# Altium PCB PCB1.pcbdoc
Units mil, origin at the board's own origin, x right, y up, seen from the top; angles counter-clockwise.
Board outline 2670.35 x 3649.61 mil, 2 copper layers (Top Layer, Bottom Layer); 40 components, 34 nets, 176 pads, 47 vias.
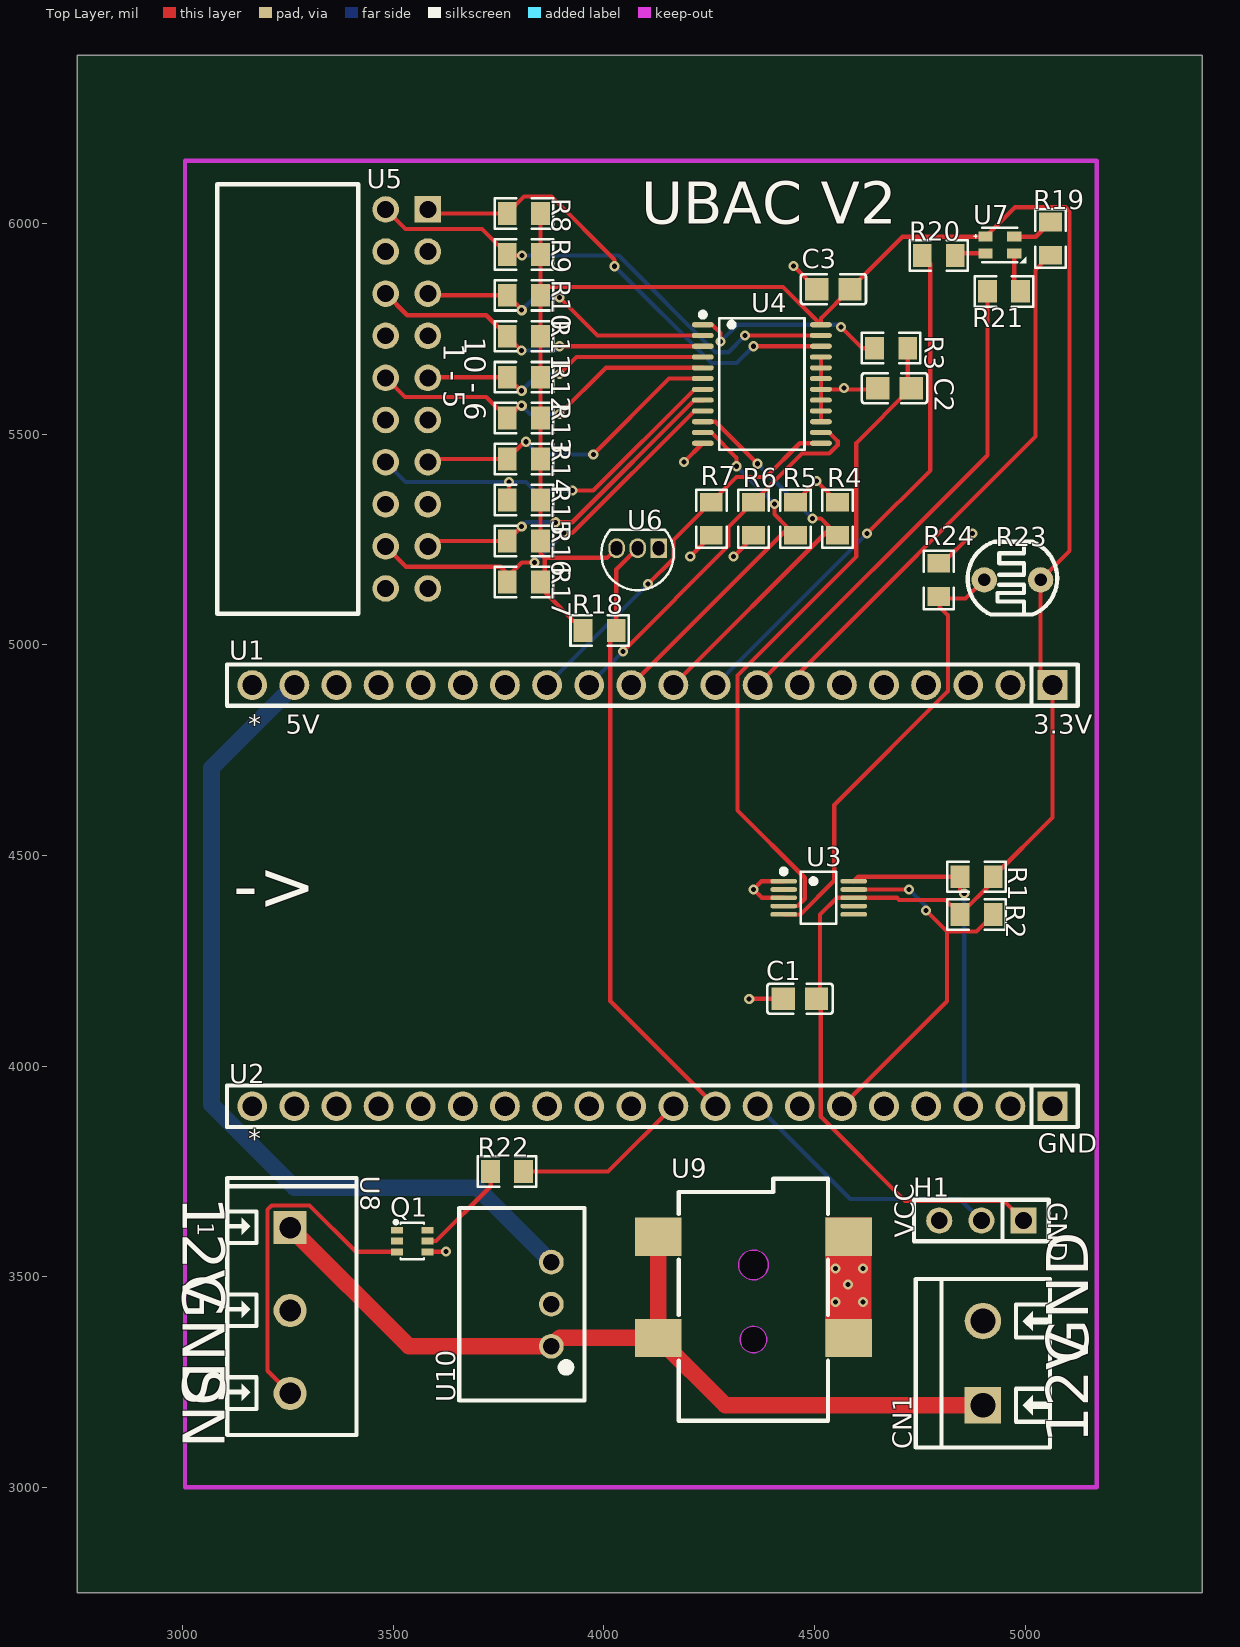
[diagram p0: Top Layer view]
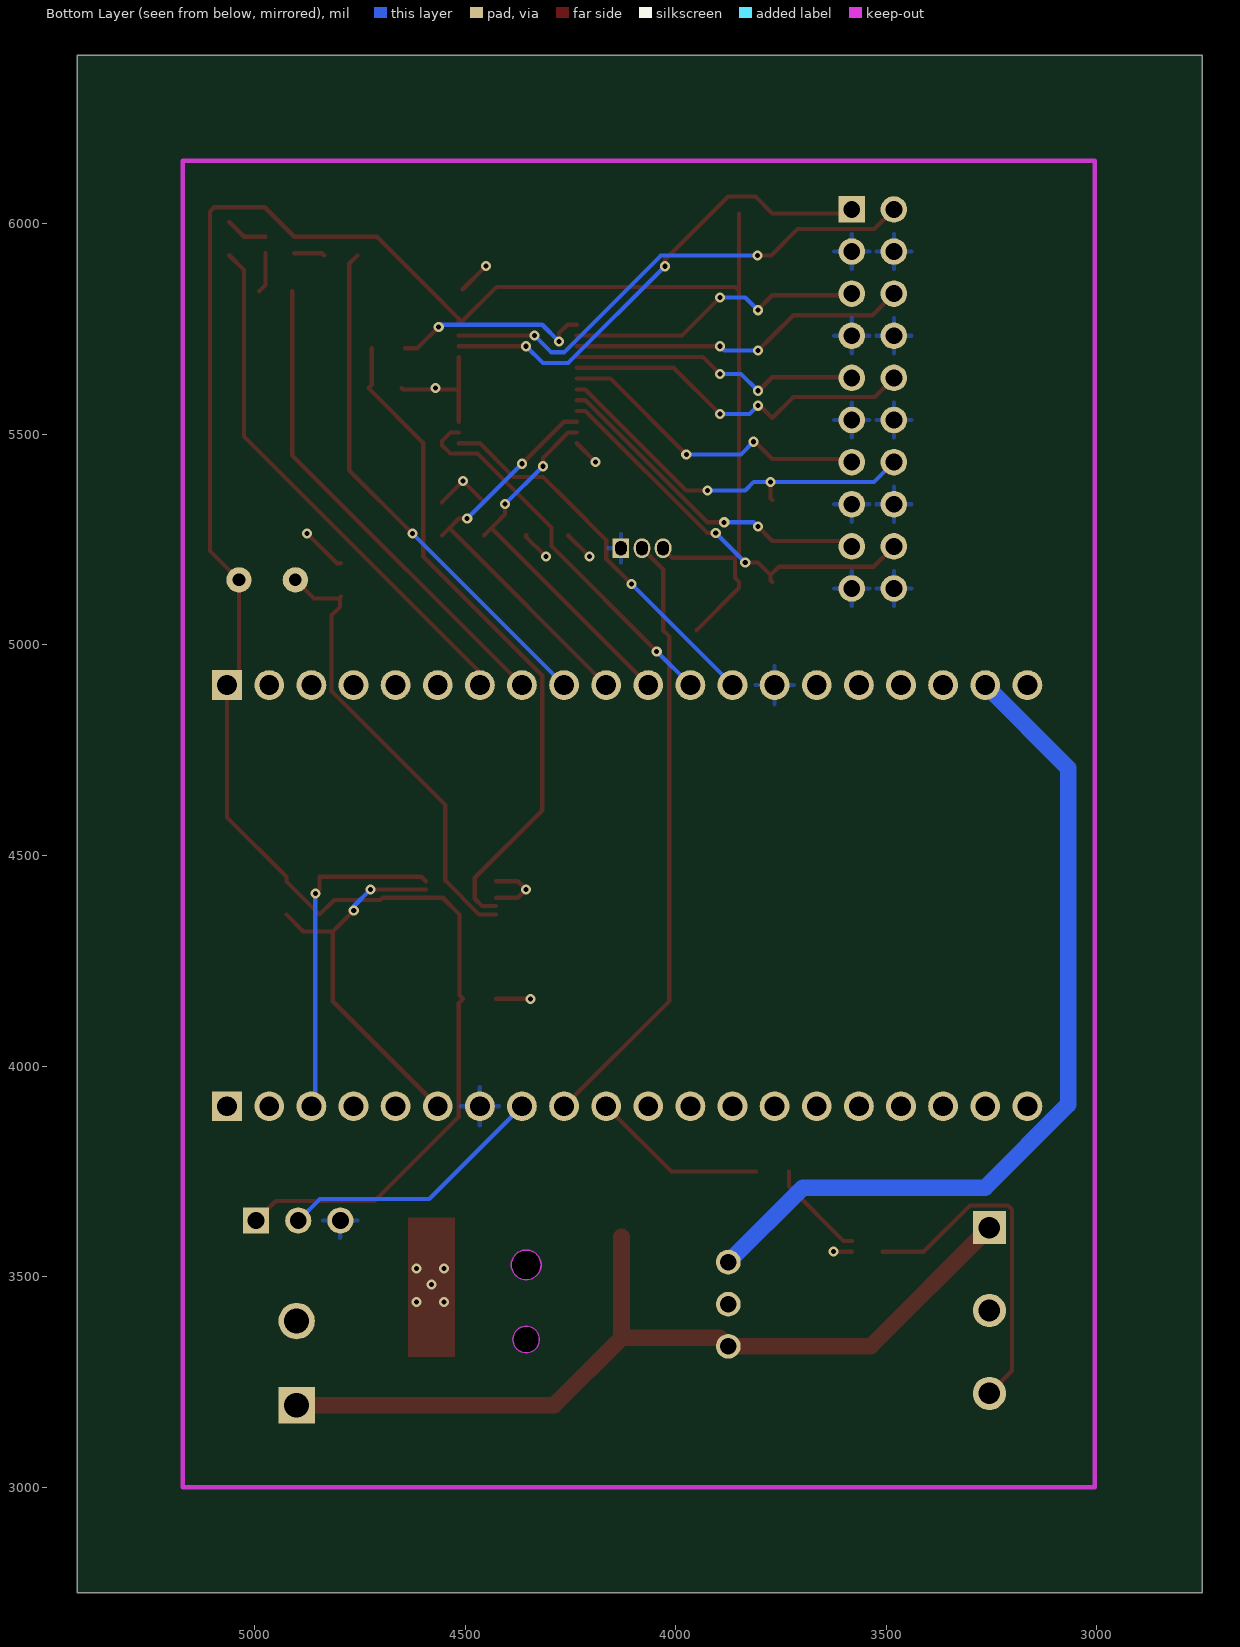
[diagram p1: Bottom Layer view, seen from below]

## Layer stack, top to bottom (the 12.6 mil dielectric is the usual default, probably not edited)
Top Layer: signal copper (thickness not stored)
Dielectric: dielectric 12.6, FR-4, Dk 4.8
Bottom Layer: signal copper (thickness not stored)

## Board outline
5420.35,2750 2750,2750 2750,6399.61 5420.35,6399.61

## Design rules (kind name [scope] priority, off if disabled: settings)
BoardOutlineClearance copperThickness1oz [All] p0: genericclearance=10 ignorepadtopadclearanceinfootprint=FALSE except(0: Arc-SplitContinuation Track-SplitContinuation SMDPad-SplitContinuation THPad-SplitContinuation Via-SplitContinuation Fill-SplitContinuation Poly-SplitContinuation Region-SplitContinuation Text-SplitContinuation; 6: Track-CutoutEdge SMDPad-CutoutEdge THPad-CutoutEdge Via-CutoutEdge Region-CutoutEdge; 11.8: Track-OutlineEdge SMDPad-OutlineEdge THPad-OutlineEdge Via-OutlineEdge Fill-OutlineEdge Region-OutlineEdge Poly-OutlineEdge Text-OutlineEdge Fill-CutoutEdge)
BoardOutlineClearance copperThickness2oz [All] p0: genericclearance=10 ignorepadtopadclearanceinfootprint=FALSE except(0: Arc-SplitContinuation Track-SplitContinuation SMDPad-SplitContinuation THPad-SplitContinuation Via-SplitContinuation Fill-SplitContinuation Poly-SplitContinuation Region-SplitContinuation Text-SplitContinuation; 6: Track-CutoutEdge SMDPad-CutoutEdge THPad-CutoutEdge Via-CutoutEdge Region-CutoutEdge; 11.8: Track-OutlineEdge SMDPad-OutlineEdge THPad-OutlineEdge Via-OutlineEdge Fill-OutlineEdge Region-OutlineEdge Poly-OutlineEdge Text-OutlineEdge Fill-CutoutEdge)
Clearance copperThickness1oz [(InNet('MUX_SELECT_0') OR InNet('GND') OR InNet('MUX_SELECT_3') OR InNet('MUX_SELECT_1') OR InNet('TEMP9') OR InNet('VCC') OR InNet('SDA') OR InNet('MUX_SELECT_2') OR InNet('SCL') OR InNet('TEMP8') OR InNet('TEMP7') OR InNet('TEMP6') OR InNet('TEMP5') OR InNet('TEMP4') OR InNet('TEMP3') OR InNet('TEMP2') OR InNet('TEMP1') OR InNet('TEMP10') OR InNet('$3N394') OR InNet('FAN_CTRL') OR InNet('NTC_ADC') OR InNet('NTC_MUX') OR InNet('DH11_DATA') OR InNet('12V') OR InNet('DS18B20_DATA') OR InNet('LED_R') OR InNet('LED_G') OR InNet('LED_B') OR InNet('5V') OR InNet('$3N812') OR InNet('$6N1989') OR InNet('$6N2479') OR InNet('LDR') OR InNet('$6N2851'))] p1: gap=7 ignorepadtopadclearanceinfootprint=FALSE except(4: Track-Track; 6: Track-SMDPad SMDPad-SMDPad Track-THPad SMDPad-THPad THPad-THPad Track-Via SMDPad-Via THPad-Via Via-Via SMDPad-Fill THPad-Fill Via-Fill Fill-Fill Track-Region SMDPad-Region THPad-Region Via-Region Region-Region Track-Poly SMDPad-Poly THPad-Poly Via-Poly Fill-Poly Region-Poly Poly-Poly Track-Text SMDPad-Text THPad-Text Via-Text Fill-Text Region-Text Poly-Text Text-Text; 6.9: Track-Hole SMDPad-Hole THPad-Hole Via-Hole Fill-Hole Region-Hole Poly-Hole Text-Hole Sheet-Hole; 11.8: Track-Fill Fill-Region Track-Sheet SMDPad-Sheet THPad-Sheet Via-Sheet Fill-Sheet Region-Sheet Poly-Sheet Text-Sheet)
Clearance copperThickness2oz [All] p1: gap=7 ignorepadtopadclearanceinfootprint=FALSE except(6: Track-SMDPad SMDPad-SMDPad Track-THPad SMDPad-THPad THPad-THPad Track-Via SMDPad-Via THPad-Via Via-Via SMDPad-Fill THPad-Fill Via-Fill Fill-Fill Track-Region SMDPad-Region THPad-Region Via-Region Region-Region Track-Poly SMDPad-Poly THPad-Poly Via-Poly Fill-Poly Region-Poly Poly-Poly Track-Text SMDPad-Text THPad-Text Via-Text Fill-Text Region-Text Poly-Text Text-Text; 6.9: Track-Hole SMDPad-Hole THPad-Hole Via-Hole Fill-Hole Region-Hole Poly-Hole Text-Hole Sheet-Hole; 8: Track-Track; 11.8: Track-Fill Fill-Region Track-Sheet SMDPad-Sheet THPad-Sheet Via-Sheet Fill-Sheet Region-Sheet Poly-Sheet Text-Sheet)
DiffPairsRouting differentialPair [All] p1: maxuncoupledlength=10 minlimit=6 maxlimit=6 mostfreqgap=6 toplayer_minwidth=5 toplayer_prefwidth=10 toplayer_maxwidth=100 bottomlayer_minwidth=5 bottomlayer_prefwidth=10 bottomlayer_maxwidth=100
PasteMaskExpansion pasteMaskExpansion [All] p1: expansion=0
PlaneConnect innerPlane [All] p1: planeconnectstyle=Relief reliefexpansion=20 reliefentries=4 reliefconductorwidth=10 reliefairgap=10
PolygonConnect copperRegion [All] p1: connectstyle=Relief reliefentries=4 reliefconductorwidth=10 polygonreliefangle="90 Angle" airgapwidth=10
RoutingVias viaSize [All] p1: viastyle="Through Hole" holewidth=12.0078 minholewidth=11.811 maxholewidth=248.0314 width=24.0158 minwidth=19.685 maxwidth=393.7008
SolderMaskExpansion solderMaskExpansion [All] p1: useseparateexpansions=TRUE expansion=2 expansionbottom=2
Width copperThickness1oz [All] p1: maxlimit=100 minlimit=5 preferedwidth=10
Width copperThickness2oz [All] p1: maxlimit=100 minlimit=8 preferedwidth=10
Width copperThickness1ozLarge [All] p1: maxlimit=100 minlimit=31 preferedwidth=39

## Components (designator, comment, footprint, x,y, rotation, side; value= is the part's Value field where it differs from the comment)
C1 "CL21B104KCFNNNE" C0805 4465.49,4159.85 r0 top
C2 "CL21B105KBFNNNE" C0805 4690,5609.68 r0 top
C3 "CL21B104KCFNNNE" C0805 4545,5844.61 r0 top
CN1 "1729128_C7509570" CONN-TH_2P-P5.08_1729128 4900,3294.61 r90 top
H1 "PM254V-11-03-H85" HDR-TH_3P-P2.54-V-F 4896.24,3633.3 r180 top
Q1 "MBT3904DW1T1G" SOT-363_L2.0-W1.3-P0.65-LS2.1-TL 3545,3584.61 r0 top
R1 "0805W8F4701T5E" R0805 4885,4449.61 r180 top
R2 "0805W8F4701T5E" R0805 4885,4359.61 r180 top
R3 "0805W8F2200T5E" R0805 4682.03,5704.61 r180 top
R4 "0805W8F1003T5E" R0805 4555,5299.61 r90 top
R5 "0805W8F1003T5E" R0805 4455,5299.61 r90 top
R6 "0805W8F1003T5E" R0805 4355,5299.61 r90 top
R7 "0805W8F1003T5E" R0805 4255,5299.61 r90 top
R8 "TC0525B5602T5G" R0805 3810,6024.61 r180 top
R9 "TC0525B5602T5G" R0805 3810,5927.38 r180 top
R10 "TC0525B5602T5G" R0805 3810,5830.16 r180 top
R11 "TC0525B5602T5G" R0805 3810,5732.94 r180 top
R12 "TC0525B5602T5G" R0805 3810,5635.72 r180 top
R13 "TC0525B5602T5G" R0805 3810,5538.5 r180 top
R14 "TC0525B5602T5G" R0805 3810,5441.27 r180 top
R15 "TC0525B5602T5G" R0805 3810,5344.05 r180 top
R16 "TC0525B5602T5G" R0805 3810,5246.83 r180 top
R17 "TC0525B5602T5G" R0805 3810,5149.61 r180 top
R18 "0805W8F4701T5E" R0805 3990,5034.61 r180 top
R19 "0805W8F1000T5E_C17408" R0805 5060,5964.61 r270 top
R20 "0805W8F1000T5E_C17408" R0805 4795,5924.61 r0 top
R21 "0805W8F1800T5E" R0805 4950,5839.61 r180 top
R22 "FRC0805J102 TS" R0805 3770,3749.61 r180 top
R23 "GL5539" RES-TH_L5.1-W4.3-P3.40-D0.5 4970,5154.61 r270 top
R24 "0805W8F1002T5E" R0805 4795,5154.61 r90 top
U1 "ZX-PM2.54-1-20PY" HDR-TH_20P-P2.54-V-F 4115,4904.61 r180 top
U2 "ZX-PM2.54-1-20PY" HDR-TH_20P-P2.54-V-F 4115,3904.61 r180 top
U3 "ADS1115IDGSR" MSOP-10_L3.0-W3.0-P0.50-LS5.0-BL 4510,4399.61 r270 top
U4 "CD74HC4067SM96" SSOP-24_L8.1-W5.3-P0.65-LS7.8-BL 4375,5619.61 r270 top
U5 "HX FH254-02-10-W-H8.5 right angle pin header" HDR-TH_20P-P2.54-H-F-R2-C10-S2.54-W12.7 3531.85,5584.06 r270 top
U6 "DS18B20" TO-92-3_L4.5-W3.5-P1.27-L 4080,5229.61 r180 top
U7 "XL-B2020RGBA-HF" LED-SMD_4P-L2.1-W2.1-P1.0-BL 4940,5949.61 r0 top
U8 "MX126-5.0-03P-GN01-Cu-S-A" CONN-TH_3P-P5.00_MAX_MX126-5.0-GN01-03P-CU-S-A 3255,3419.61 r270 top
U9 "DC-050-20" DC-IN-SMD_DC-050-20A 4355,3474.61 r180 top
U10 "K7805-1000R3" PWRM-TH_YLPTEC_K78XX-1000R3 3875,3434.61 r90 top

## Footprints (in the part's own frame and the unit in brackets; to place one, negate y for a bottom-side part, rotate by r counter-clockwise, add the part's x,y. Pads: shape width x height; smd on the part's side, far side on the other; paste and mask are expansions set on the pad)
C0805 [mm]
  rect 1.41x1.35 smd: 1(-1,0) 2(1,0)
  silkscreen extent -1.96,-0.9 1.96,0.9
CONN-TH_2P-P5.08_1729128 [mm]
  rect 2.2x2.2 hole 1.5: 1(-2.54,0)
  round 2.2 hole 1.5: 2(2.54,0)
  silkscreen extent -5.08,-4.05 5.08,4.05
CONN-TH_3P-P5.00_MAX_MX126-5.0-GN01-03P-CU-S-A [mm]
  rect 2x2 hole 1.3: 1(-5,0)
  round 2 hole 1.3: 2(0,0) 3(5,0)
  silkscreen extent -8,-3.81 7.5,4
DC-IN-SMD_DC-050-20A [mm]
  rect 2.8x2.3 smd: 1(5.75,3.05) 1(5.75,-3.05) 2(-5.75,3.05) 3(-5.75,-3.05)
  Board Outline Layer circle w0.005: c0,3.15 r0.8
  Board Outline Layer circle w0.005: c0,-1.35 r0.9
  Board Outline Layer region: -0.8,3.15 -0.721,3.497 -0.499,3.775 -0.178,3.93 0.178,3.93 0.499,3.775 0.721,3.497 0.8,3.15 0.8,3.15 0.721,2.803 0.499,2.525 0.178,2.37 -0.178,2.37 -0.499,2.525 -0.721,2.803 -0.8,3.15
  Board Outline Layer region: -0.9,-1.35 -0.811,-0.96 -0.561,-0.646 -0.2,-0.473 0.2,-0.473 0.561,-0.646 0.811,-0.96 0.9,-1.35 0.9,-1.35 0.811,-1.741 0.561,-2.054 0.2,-2.228 -0.2,-2.228 -0.561,-2.054 -0.811,-1.741 -0.9,-1.35
  Multi-Layer board cut-out: -0.8,3.15 -0.721,3.497 -0.499,3.775 -0.178,3.93 0.178,3.93 0.499,3.775 0.721,3.497 0.8,3.15 0.8,3.15 0.721,2.803 0.499,2.525 0.178,2.37 -0.178,2.37 -0.499,2.525 -0.721,2.803 -0.8,3.15
  Multi-Layer board cut-out: -0.9,-1.35 -0.811,-0.96 -0.561,-0.646 -0.2,-0.473 0.2,-0.473 0.561,-0.646 0.811,-0.96 0.9,-1.35 0.9,-1.35 0.811,-1.741 0.561,-2.054 0.2,-2.228 -0.2,-2.228 -0.561,-2.054 -0.811,-1.741 -0.9,-1.35
  silkscreen extent -4.5,-6.55 4.5,8.05
HDR-TH_3P-P2.54-V-F [mil]
  rect 62x62 hole 40.16: 1(-100,0)
  round 62 hole 40.16: 2(0,0) 3(100,0)
  silkscreen extent -160,-49 160,49
HDR-TH_20P-P2.54-H-F-R2-C10-S2.54-W12.7 [mm]
  rect 1.6x1.6 hole 1.02: 1(-11.43,1.27)
  round 1.6 hole 1.02: 2(-11.43,-1.27) 3(-8.89,1.27) 4(-8.89,-1.27) 5(-6.35,1.27) 6(-6.35,-1.27) 7(-3.81,1.27) 8(-3.81,-1.27) 9(-1.27,1.27) 10(-1.27,-1.27) 11(1.27,1.27) 12(1.27,-1.27) 13(3.81,1.27) 14(3.81,-1.27) 15(6.35,1.27) 16(6.35,-1.27) 17(8.89,1.27) 18(8.89,-1.27) 19(11.43,1.27) 20(11.43,-1.27)
  silkscreen extent -12.95,-11.43 12.95,-2.92
HDR-TH_20P-P2.54-V-F [mm]
  rect 1.8x1.8 hole 1.2: 1(-24.13,0)
  round 1.8 hole 1.2: 2(-21.59,0) 3(-19.05,0) 4(-16.51,0) 5(-13.97,0) 6(-11.43,0) 7(-8.89,0) 8(-6.35,0) 9(-3.81,0) 10(-1.27,0) 11(1.27,0) 12(3.81,0) 13(6.35,0) 14(8.89,0) 15(11.43,0) 16(13.97,0) 17(16.51,0) 18(19.05,0) 19(21.59,0) 20(24.13,0)
  silkscreen extent -25.65,-1.25 25.65,1.25
LED-SMD_4P-L2.1-W2.1-P1.0-BL [mm]
  rect 0.85x0.6 smd: 1(0.87,-0.5) 2(-0.87,-0.5) 3(-0.87,0.5) 4(0.87,0.5)
  silkscreen extent -1.58,-1.1 1.6,1.05
MSOP-10_L3.0-W3.0-P0.50-LS5.0-BL [mm]
  oval 0.28x1.62 smd: 1(-1,-2.11) 2(-0.5,-2.11) 3(0,-2.11) 4(0.5,-2.11) 5(1,-2.11) 6(1,2.11) 7(0.5,2.11) 8(0,2.11) 9(-0.5,2.11) 10(-1,2.11)
  silkscreen extent -1.74,-2.26 1.58,1.07
PWRM-TH_YLPTEC_K78XX-1000R3 [mm]
  round 1.5 hole 1: 1(-2.54,0) 2(0,0) 3(2.54,0)
  silkscreen extent -5.8,-2 5.8,5.55
R0805 [mm]
  rect 1.133x1.377 smd: 1(-1,0) 2(1,0)
  silkscreen extent -1.76,-0.92 1.76,0.92
RES-TH_L5.1-W4.3-P3.40-D0.5 [mil]
  round 60 hole 30: 1(0,66.93) 2(0,-66.93)
  silkscreen extent -91,-106 83,106
SOT-363_L2.0-W1.3-P0.65-LS2.1-TL [mm]
  rect 0.7x0.42 smd: 1(-0.92,0.65) 2(-0.92,0) 3(-0.92,-0.65) 4(0.92,-0.65) 5(0.92,0) 6(0.92,0.65)
  silkscreen extent -1.09,-1.1 0.7,1.24
SSOP-24_L8.1-W5.3-P0.65-LS7.8-BL [mil]
  oval 12.13x52.13 smd: 1(-140.75,-140.24) 2(-115.16,-140.24) 3(-89.57,-140.24) 4(-63.98,-140.24) 5(-38.39,-140.24) 6(-12.79,-140.24) 7(12.8,-140.24) 8(38.39,-140.24) 9(63.98,-140.24) 10(89.57,-140.24) 11(115.16,-140.24) 12(140.75,-140.24) 13(140.75,140.24) 14(115.16,140.24) 15(89.57,140.24) 16(63.98,140.24) 17(38.39,140.24) 18(12.8,140.24) 19(-12.79,140.24) 20(-38.39,140.24) 21(-63.98,140.24) 22(-89.57,140.24) 23(-115.16,140.24) 24(-140.75,140.24)
  silkscreen extent -171,-146 157,101
TO-92-3_L4.5-W3.5-P1.27-L [mm]
  rect 1x1.2 hole 0.7 slot 0.85 at 90 deg: 1(-1.27,0)
  oval 1x1.2 hole 0.7 slot 0.85 at 90 deg: 2(0,0) 3(1.27,0)
  silkscreen extent -2.19,-1.1 2.19,2.52

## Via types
v1: diameter 24.02, hole 12.01, Top Layer to Bottom Layer, 47 vias

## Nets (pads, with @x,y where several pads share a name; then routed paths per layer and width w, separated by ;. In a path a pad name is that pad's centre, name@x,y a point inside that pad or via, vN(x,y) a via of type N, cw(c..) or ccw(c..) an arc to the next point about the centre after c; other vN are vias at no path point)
5V: U1.19 U10.3 | length 2039.4
  Bottom Layer w39.37: U1.19 3068.15,4707.75 3068.15,3908.38 3265,3711.53 3698.07,3711.53 U10.3
12V: CN1.1 U8.1 U9.1 U10.1 | length 2076.4
  Top Layer w39.37: U8.1 3536.85,3334.61 U10.1 3894.92,3354.53 U9.1@4128.62,3354.53 ; U9.1@4128.62,3594.68 U9.1@4128.62,3354.53 ; CN1.1 4288.54,3194.61 U9.1@4128.62,3354.53
$3N394: Q1.3 U8.3 | length 815.7
  Top Layer w10: U8.3 3201.26,3276.5 3201.26,3659.02 3211.26,3669.02 3301.26,3669.02 3411.26,3559.02 Q1.3
$3N812: Q1.5 R22.2 | length 239.1
  Top Layer w10: Q1.5 3601.22,3584.61 3731.22,3714.61 3731.22,3749.02 R22.2
$6N1989: R19.1 U7.4 | length 100.1
  Top Layer w10: U7.4 5025.31,5969.29 R19.1
$6N2479: R21.1 U7.1 | length 96.6
  Top Layer w10: U7.1 4974.25,5854.73 R21.1
$6N2851: R20.2 U7.2 | length 73.6
  Top Layer w10: R20.2 4839.69,5929.92 U7.2
DH11_DATA: H1.2 U2.8 | length 643.6
  Bottom Layer w10: U2.8 4585,3684.61 4844.93,3684.61 H1.2
DS18B20_DATA: R18.1 U2.9 U6.2 | length 1455.5
  Top Layer w10: U6.2 4029.37,5178.98 R18.1 4015,5020.24 4015,4154.61 U2.9
FAN_CTRL: R22.1 U2.10 | length 419.8
  Top Layer w10: R22.1 4010,3749.61 U2.10
GND: C1.1 C2.1 C3.1 CN1.2 H1.3 Q1.4 R4.2 R5.2 R6.1 R7.1 R24.2 U1.14 U2.1 U2.7 U3.1 U3.3 U4.12 U4.15 U4.16 U4.17 U4.18 U4.19 U4.20 U4.21 U5.3 U5.4 U5.7 U5.8 U5.11 U5.12 U5.15 U5.16 U5.19 U5.20 U6.1 U8.2 U9.2 U9.3 U10.2 | length 1110.1
  Top Layer w10: Q1.4 3625,3559.02 v1(3625,3559.61) ; v1(4190,5434.61) 4190.51,5434.61 U4.12 ; v1(4205,5209.61) 4255,5259.61 R7.1 ; v1(4308.14,5209.61) 4355,5256.47 R6.1 ; v1(4345,4159.61) 4345.24,4159.85 C1.1 ; U3.3 4375,4399.61 v1(4355,4419.61) 4374.37,4438.98 U3.1 ; v1(4450,5899.61) 4450.63,5899.61 C3.1 ; R5.2 v1@4505,5388.98 ; v1(4505,5389.61) v1@4505,5388.98 ; U4.15 U4.16 U4.17 U4.18 ; U4.21 U4.20 U4.19 U4.18 ; R4.2 v1@4505,5388.98 ; C2.1 4647.76,5606.81 U4.18 ; R24.2 4804.37,5193.98 v1(4875,5264.61)
  other v1: 4550,3440.1 4615,3440.1 4580,3481.04 4550,3519.61 4615,3519.61 4570,5609.61
LDR: R23.2 R24.1 U3.5 | length 1073.1
  Top Layer w10: U3.5 4466.93,4360.24 4546.93,4440.24 4546.93,4620.24 4816.93,4890.24 4816.93,5070.24 4796.93,5090.24 R24.1@4796.93,5110.24 ; R24.1 R24.1@4796.93,5110.24 ; R23.2 4858.7,5110.24 R24.1@4796.93,5110.24
LED_B: R20.1 U1.9 | length 1239.3
  Top Layer w10: v1(4625,5264.61) 4775,5414.61 4775,5905.24 R20.1
  Bottom Layer w10: U1.9 v1(4625,5264.61)
LED_G: R19.2 U1.7 | length 1267.1
  Top Layer w10: U1.7 4465,4934.61 5025,5494.61 5025,5890.24 R19.2
LED_R: R21.2 U1.8 | length 1161
  Top Layer w10: U1.8 4910.63,5450.23 R21.2
MUX_SELECT_0: R4.1 U1.10 U4.10 | length 960.9
  Top Layer w10: U1.10 4535,5274.6 R4.1@4535,5280.24 ; U4.10 4265.2,5530.04 v1(4365,5430.24) ; v1(4495,5300.24) 4515,5300.24 R4.1@4535,5280.24 ; R4.1 R4.1@4535,5280.24
  Bottom Layer w10: v1(4365,5430.24) v1(4495,5300.24)
MUX_SELECT_1: R5.1 U1.11 U4.11 | length 875.7
  Top Layer w10: U1.11 4435,5274.6 R5.1@4435,5280.24 ; U4.11@4235,5504.21 4255,5504.21 4315,5444.21 v1(4315,5424.21) ; v1(4405,5334.21) 4405,5310.24 R5.1@4435,5280.24 ; R5.1 R5.1@4435,5280.24
  Bottom Layer w10: v1(4315,5424.21) v1(4405,5334.21)
MUX_SELECT_2: R6.2 U1.12 U4.14 | length 910.1
  Top Layer w10: v1(4045,4984.6) 4295,5234.6 4295,5278.98 R6.2 4470.23,5454.21 4535,5454.21 4555,5474.21 4555,5484.21 4534.76,5504.45 U4.14
  Bottom Layer w10: U1.12 v1(4045,4984.6)
MUX_SELECT_3: R7.2 U1.13 U4.13 | length 914.1
  Top Layer w10: v1(4105,5144.6) 4165,5204.6 4165,5248.98 R7.2 4315,5398.98 4385,5398.98 4464.88,5478.86 U4.13
  Bottom Layer w10: U1.13 v1(4105,5144.6)
NTC_ADC: C2.2 R3.1 U3.4 | length 1605
  Top Layer w10: U3.4 4459.61,4379.92 4476.93,4397.24 4476.93,4447.24 4316.93,4607.24 4316.93,4927.24 4599.37,5209.68 4599.37,5479.68 C2.2 4721.4,5617.65 R3.1
NTC_MUX: R3.2 U4.1 | length 475.8
  Top Layer w10: U4.1 4256.91,5760.36 4276.91,5740.36 v1(4276.91,5720.36) ; v1(4562.66,5754.61) 4612.66,5704.61 R3.2
  Bottom Layer w10: v1(4276.91,5720.36) 4316.91,5760.36 4556.91,5760.36 v1(4562.66,5754.61)
SCL: R1.2 U2.3 U3.10 | length 810
  Top Layer w10: U3.10 4603.7,4449.61 R1.2 4845.63,4419.61 v1(4855.63,4409.61)
  Bottom Layer w10: v1(4855.63,4409.61) 4855.63,3913.98 U2.3
SDA: R2.1 U2.6 U3.9 | length 913.6
  Top Layer w10: U2.6 4814.37,4153.97 4814.37,4319.61 ; U3.9 4593.39,4419.61 v1(4724.37,4419.61) ; v1(4764.37,4369.61) 4814.37,4319.61 ; R2.1 4884.37,4319.61 4814.37,4319.61
  Bottom Layer w10: v1(4724.37,4419.61) 4764.37,4379.61 v1(4764.37,4369.61)
TEMP1: R9.2 U4.23 U5.2 | length 1190.5
  Top Layer w10: U5.2 3528.53,5987.38 3710.63,5987.38 R9.2 3773.25,5924.77 v1(3805.24,5924.77) ; v1(4335.24,5734.77) U4.23
  Bottom Layer w10: v1(3805.24,5924.77) 4035.24,5924.77 4265.24,5694.77 4295.24,5694.77 v1(4335.24,5734.77)
TEMP2: R11.2 U4.3 U5.6 | length 812.9
  Top Layer w10: U5.6 3532.97,5782.94 3720.63,5782.94 R11.2 v1(3804.39,5699.18) ; v1(3894.39,5709.18) U4.3
  Bottom Layer w10: v1(3804.39,5699.18) 3884.39,5699.18 v1(3894.39,5709.18)
TEMP3: R13.2 U4.5 U5.10 | length 858.6
  Top Layer w10: U5.10 3527.41,5588.5 3720.63,5588.5 R13.2 3800.13,5568 v1(3804.76,5568) ; v1(3894.76,5548) 4004.76,5658 U4.5
  Bottom Layer w10: v1(3804.76,5568) 3824.76,5548 v1(3894.76,5548)
TEMP4: R15.2 U4.7 U5.14 | length 924.6
  Top Layer w10: R15.2 3774.76,5348.18 v1(3774.76,5386.81) ; v1(3924.76,5366.81) 3974.76,5366.81 4214.76,5606.81 U4.7
  Bottom Layer w10: U5.14 3529.1,5386.81 v1(3774.76,5386.81) 3814.76,5386.81 3834.76,5366.81 v1(3924.76,5366.81)
TEMP5: R17.2 U4.9 U5.18 | length 960.5
  Top Layer w10: U5.18 3530.28,5185.63 3754.76,5185.63 R17.2@3774.76,5165.63 ; R17.2 3774.76,5153.74 R17.2@3774.76,5165.63 ; v1(3834.76,5195.63) 3804.76,5195.63 R17.2@3774.76,5165.63 ; v1(3904.76,5265.63) 3924.76,5265.63 4214.76,5555.63 U4.9
  Bottom Layer w10: v1(3834.76,5195.63) v1(3904.76,5265.63)
TEMP6: R16.2 U4.8 U5.17 | length 796.8
  Top Layer w10: U5.17 3594.61,5246.83 R16.2 v1(3804.76,5281.22) ; v1(3884.76,5291.22) 3924.76,5291.22 4214.76,5581.22 U4.8
  Bottom Layer w10: v1(3804.76,5281.22) 3814.76,5291.22 v1(3884.76,5291.22)
TEMP7: R14.2 U4.6 U5.13 | length 759.9
  Top Layer w10: U5.13 3589.06,5441.27 R14.2 3811.75,5482.4 v1(3814.76,5482.4) ; v1(3974.76,5452.4) 4154.76,5632.4 U4.6
  Bottom Layer w10: v1(3814.76,5482.4) 3844.76,5452.4 v1(3974.76,5452.4)
TEMP8: R12.2 U4.4 U5.9 | length 700
  Top Layer w10: U5.9 3583.5,5635.72 R12.2 3802.76,5603.59 v1(3804.76,5603.59) ; v1(3894.76,5643.59) 3934.76,5683.59 U4.4
  Bottom Layer w10: v1(3804.76,5603.59) 3844.76,5643.59 v1(3894.76,5643.59)
TEMP9: R10.2 U4.2 U5.5 | length 719.6
  Top Layer w10: U5.5 3585.75,5830.16 R10.2 3804.76,5796.03 v1(3804.76,5794.77) ; v1(3894.76,5824.77) 3984.76,5734.77 U4.2
  Bottom Layer w10: v1(3804.76,5794.77) 3834.76,5824.77 v1(3894.76,5824.77)
TEMP10: R8.2 U4.22 U5.1 | length 1143.3
  Top Layer w10: U5.1 3591.3,6024.61 R8.2 3810.63,6064.61 3875.24,6064.61 4025.24,5914.61 v1(4025.24,5899.18) ; v1(4355.24,5709.18) U4.22
  Bottom Layer w10: v1(4025.24,5899.18) 4255.24,5669.18 4315.24,5669.18 v1(4355.24,5709.18)
VCC: C1.2 C3.2 H1.1 R1.1 R2.2 R8.1 R9.1 R10.1 R11.1 R12.1 R13.1 R14.1 R15.1 R16.1 R17.1 R18.2 R23.1 U1.1 U3.8 U4.24 U6.3 U7.3 | length 5883.7
  Top Layer w10: R8.1 R9.1 R10.1@3849.37,5840.16 ; R18.2 3849.37,5135.87 R17.1 3859.37,5159.61 3859.37,5206.83 ; U6.3 4007.22,5206.83 3859.37,5206.83 ; H1.1 4949.69,3679.85 4714.86,3679.85 4514.86,3879.85 4514.86,4149.85 C1.2 4513.07,4168.06 4513.07,4359.61 4553.07,4399.61 U3.8 4695.63,4399.61 4700.67,4394.57 4810.67,4394.57 R2.2 4924.37,4438.35 R1.1 5065,4590.24 U1.1 5036.93,4932.68 R23.1 5105.75,5223.43 5105.75,6029.29 5095.75,6039.29 4975.75,6039.29 U7.3 4709.06,5969.29 C3.2 4515.24,5775.48 U4.24 4425.43,5850.16 3859.37,5850.16 R10.1@3849.37,5840.16 ; R10.1@3849.37,5840.16 R10.1 R11.1 R12.1 R13.1 R14.1 R15.1 R16.1 3849.37,5216.83 3859.37,5206.83
pads on no net: Q1.1 Q1.2 Q1.6 U1.2 U1.3 U1.4 U1.5 U1.6 U1.15 U1.16 U1.17 U1.18 U1.20 U2.2 U2.4 U2.5 U2.11 U2.12 U2.13 U2.14 U2.15 U2.16 U2.17 U2.18 U2.19 U2.20 U3.2 U3.6 U3.7

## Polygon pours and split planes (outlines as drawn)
GND on Bottom Layer (solid, remove dead copper, pour order 0): 3005,6149.61 5170.35,6149.61 5170.35,3000 3005,3000

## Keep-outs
Board Outline Layer:
  lines w10: 3005,3000 5170.35,3000 5170.35,6149.61 3005,6149.61 3005,3000

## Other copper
Top Layer:
  region net GND: 4525,3639.61 4525,3309.61 4635,3309.61 4635,3639.61

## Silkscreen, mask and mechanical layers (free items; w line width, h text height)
Top Silkscreen Layer:
  text "UBAC V2" at 4088.85,5999.61 h100
  text "10 - 6" at 3670,5731.96 h50 r270
  text "1 - 5" at 3620,5716.51 h50 r270
  text "*" at 3155,4789.61 h45
  text "5V" at 3245,4789.61 h45
  text "3.3V" at 5020,4789.61 h45
  text "->" at 3120,4369.61 h120
  text "*" at 3155,3804.61 h45
  text "GND" at 5030,3794.61 h45
  text "12V" at 3000,3689.61 h100 r270
  text "GND" at 5054.91,3676.15 h45 r270
  text "VCC" at 4735.09,3592.3 h45 r90
  text "GND" at 3000,3505.76 h100 r270
  text "GND" at 5150,3293.46 h100 r90
  text "SN" at 3000,3280.76 h100 r270
  text "12V" at 5150,3104.61 h100 r90
Mech6:
  lines w10: 3154.5,3824.61 5034.5,3824.61 ; 3154.5,4984.6 5034.5,4984.6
